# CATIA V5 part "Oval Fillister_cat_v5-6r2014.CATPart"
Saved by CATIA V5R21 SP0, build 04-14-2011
Part number: Oval Fillister
Bounding box of the stored display mesh (mm): x -5 to 5, y -5 to 5, z -7 to 4
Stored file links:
  D:\CATIA V5R21 E-RESOURCES\CATIA-V5R21\catia-v5r21-prt\c16-catia-v5r20-prt\c16-catia-v5r21-tut01\CAT_V5R21_Oval Fillister.CATPart
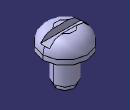
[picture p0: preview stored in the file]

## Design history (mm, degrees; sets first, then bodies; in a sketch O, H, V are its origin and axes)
Body1 (main body)
  Sketch1 on xy-plane, origin (0, 0, 0), H (1, 0, 0), V (0, 1, 0)
    circle A1 centre (0, 0) radius 5
    radius A1 = 5
  Pad1: profile Sketch1, direction (0, 0, 1), length 4
  Sketch2 on face of Pad1, origin (0, 0, 0), H (1, 0, 0), V (0, -1, 0)
    circle A1 centre (0, 0) radius 2.5
    radius A1 = 2.5
  Pad2: profile Sketch2, direction (0, 0, -1), length 6
  Sketch3 on face of Pad2, origin (0, 0, -6), H (1, 0, 0), V (0, -1, 0)
    circle A1 centre (0, 0) radius 2
    radius A1 = 2
  Pad3: profile Sketch3, direction (0, 0, -1), length 1
  Fillet1: radius 3, on 1 edge
  Sketch4 on yz-plane, origin (0, 0, 0), H (0, 1, 0), V (0, 0, 1)
    line L1 (-1, 4.5549) -> (1, 4.5549)
    line L2 (1, 4.5549) -> (1, 2.5)
    line L3 (1, 2.5) -> (-1, 2.5)
    line L4 (-1, 2.5) -> (-1, 4.5549)
    distance H L3 = 2.5
    distance L2 V = 1
    length L1 = 2
    horizontal: L1 H, L3 H
    vertical: L2 V, L4 V
  Pocket1: profile Sketch4, direction (-1, 0, 0), length 8, mirrored extent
